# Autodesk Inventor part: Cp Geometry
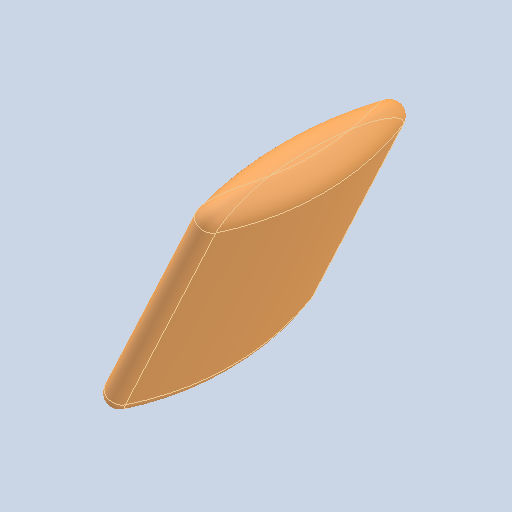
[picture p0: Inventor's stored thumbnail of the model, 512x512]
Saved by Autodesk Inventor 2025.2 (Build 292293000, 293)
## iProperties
Created: 2025-04
Part Number: Cp Geometry
Material: Generic
Description: PART-Cp Geometry-DESC
Document SubType Name: Modeling
Designer: BennF
Density: 1 g/cm^3
Appearance: Default
Author: BennF
Revision Number: NONE
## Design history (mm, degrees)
feature "Solid"
body "Solid1"
